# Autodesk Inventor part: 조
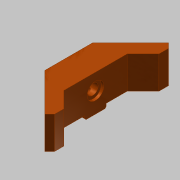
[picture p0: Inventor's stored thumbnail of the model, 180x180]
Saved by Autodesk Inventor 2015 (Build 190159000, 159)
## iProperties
Created: 2019-04
Part Number: 조
Material: 알루미늄 6061
Document SubType Name: Modeling
Designer: mduedu
Density: 1 g/cm^3
Appearance: 매끄러움 - 연한 주황색
Author: mduedu
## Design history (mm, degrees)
sketch "스케치1"
  geometry: L1 (45.962, 0)-(0, -45.962); L2 (0, -45.962)-(-45.962, 0); L3 (-45.962, 0)-(0, 45.962); L4 (0, 45.962)-(45.962, 0); L5 (45.962, 0)-(-45.962, 0); L6 (0, -45.962)-(0, 45.962); 1 further point
  constraints: 12 end point, 2 midpoint, 2 parallel, 2 perpendicular, 1 horizontal
  dimensions: "d0" = 65 distance of L1.end L2.end
extrude "돌출1" new body sketch "스케치1" distance "d2" = 27; taper "d3" = 0 deg
chamfer "모따기1" distance "d4" = 25; stored, may be unused: second distance "d5" = 2, angle "d6" = 45 deg
sketch "스케치2"
  geometry: L1 (-17.678, 28.284)-(-45.962, 0) reference; L2 (-17.678, 28.284)-(17.678, 28.284) reference; L3 (45.962, 0)-(17.678, 28.284) reference; L4 (-45.962, 0)-(0, -45.962) reference; L5 (0, -45.962)-(45.962, 0) reference; L6 (-23.536, 8.284)-(23.536, 8.284); L7 (-23.536, 8.284)-(-38.891, -7.071); L8 (38.891, -7.071)-(23.536, 8.284); 1 further point
  constraints: 6 end point, 3 parallel, 2 point on line
  dimensions: "d7" = 20 distance between parallel lines of L6 L2; "d8" = 10 distance between parallel lines of L1 L7; "d9" = 10 distance between parallel lines of L3 L8
extrude "돌출2" cut sketch "스케치2" stored distance "d10" = 27; taper "d11" = 0 deg
sketch "스케치3"
  geometry: L1 (63.64, -27)-(63.64, 0) reference; L2 (56.569, -27)-(63.64, -27) reference; L3 (-28.284, -27)-(-28.284, 0) reference; L4 (-28.284, -27)-(-21.213, -27) reference; L5 (63.64, -27)-(25.678, -27); L6 (25.678, -27)-(25.678, -24); L7 (25.678, -24)-(63.64, -24); L8 (63.64, -24)-(63.64, -27); L9 (-28.284, -27)-(9.678, -27); L10 (9.678, -27)-(9.678, -24); L11 (9.678, -24)-(-28.284, -24); L12 (-28.284, -24)-(-28.284, -27); L13 (41.213, 0)-(-5.858, 0) reference; L14 (17.678, -27)-(17.678, 0)
  constraints: 18 end point, 4 parallel, 2 horizontal, 2 perpendicular, 1 midpoint, 1 symmetric about line
  dimensions: "d12" = 3 distance between parallel lines of L5 L7; "d14" = 16 distance between parallel lines of L10 L6
extrude "돌출3" cut sketch "스케치3" stored distance "d15" = 27; taper "d16" = 0 deg
sketch "스케치4"
  geometry: L1 (31.536, -27)-(15.536, -27) reference; L2 (31.536, -24)-(47.071, -24) reference; 3 further points
  constraints: 1 midpoint, 1 vertical alignment
  dimensions: "d17" = 12 distance from line of L2 point (23.536, -12)
hole "구멍1" sketch "스케치4" at (23.536, -12) diameter "d18" = 8; stored, may be unused: countersink angle "d22" = 90 deg, drill point angle "d24" = 118 deg; dims "d19" = 6, "d20" = 12.5, "d21" = 2, "d23" = 14
node "작업 평면1"
sketch "스케치5"
  geometry: L1 (0, -15)-(0, 0); L2 (-50, -4)-(50, -4); L3 (50, -4)-(50, -1.75); L4 (-50, -1.75)-(-50, -4); L5 (12, -1.75)-(12, -2.75); L6 (12, -2.75)-(-12, -2.75); L7 (-12, -2.75)-(-12, -1.75); L8 (50, -1.75)-(12, -1.75); L9 (-12, -1.75)-(-50, -1.75); C1 r 4 at (0, 0) reference; 2 further points
  constraints: 18 end point, 4 parallel, 2 midpoint, 2 vertical, 2 vertical alignment, 1 collinear, 1 horizontal, 1 perpendicular, 1 tangent
  dimensions: "d26" = 2.5 diameter of L6 L2; "d28" = 4.5 diameter of L8 L2; "d29" = 24 distance of L5.end L6.end; "d30" = 100 distance between parallel lines of L3 L4
revolve "회전1" sketch "스케치5" stored, may be unused: angle "d31" = 90 deg
chamfer "모따기2" distance "d32" = 5; stored, may be unused: second distance "d33" = 2, angle "d34" = 45 deg
chamfer "모따기3" distance "d35" = 1; stored, may be unused: second distance "d36" = 2, angle "d37" = 45 deg
node "솔리드1"
other parameters: "d25" = -5
